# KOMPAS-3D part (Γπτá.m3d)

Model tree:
1. Эскиз:1
2. Операция выдавливания:1
     Расстояние 1 = 1
3. Эскиз:4
4. Операция выдавливания:4
     Расстояние 1 = 9
5. Эскиз:5
6. Операция выдавливания:5
     Расстояние 1 = 1.5
7. Скругление:5
     Радиус = 1
8. Скругление:6
     Радиус = 0.2
9. Эскиз:7
10. Вырезать элемент выдавливания:1
     Расстояние 1 = 0.5
11. Массив по концентрической сетке:1  (with: Вырезать элемент выдавливания:1)  (labels: Экземпляр ( 1, 1 ); Экземпляр ( 1, 2 ); Экземпляр ( 1, 3 ); Экземпляр ( 1, 4 ))
     N 2 = 6; Шаг 2 = 360; Номер 2 = 1
12. Эскиз:8
13. Операция выдавливания:7
     Расстояние 1 = 2
14. Эскиз:9
15. Операция выдавливания:8
     Расстояние 1 = 2
16. Эскиз:10
17. Операция выдавливания:9
     Расстояние 1 = 1
18. Скругление:7
     Радиус = 0.2
19. Эскиз:11
20. Вырезать элемент выдавливания:2
     Расстояние 1 = 0.1
21. Скругление:9
     Радиус = 0.1

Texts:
  Сплав АЛ8  ГОСТ 1583-93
